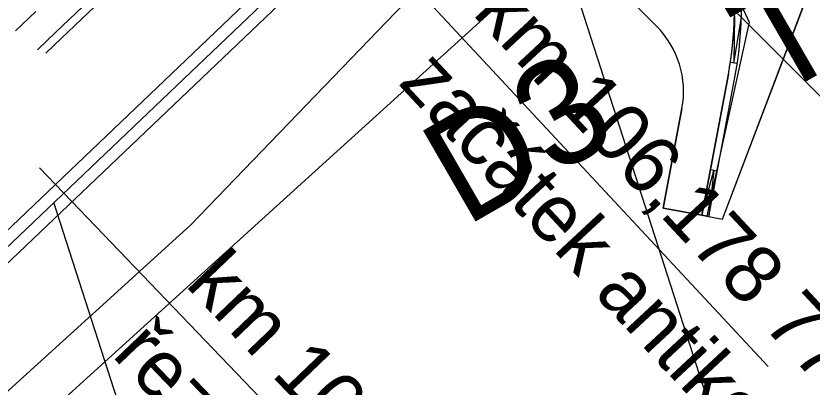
# Model space of a CAD drawing. Extents: x -759005 to -757278, y -1175311 to -1173953.
# Drawn here: x -758411.96 to -758394.73, y -1174860.97 to -1174852.94 of the extents above; entities that cross this region are included whole.
import ezdxf

# ---------------------------------------------------------------- set-up
doc = ezdxf.new("R2010")
doc.units = 0
for name, color, linetype in [('__NOR-dočasný zábor', 7, 'Continuous'), ('__NOR-trvalý zábor', 7, 'Continuous'), ('_NOR-návrh silná', 7, 'Continuous'), ('_NOR-návrh tenká', 7, 'Continuous'), ('_NOR-popis', 7, 'Continuous'), ('_NOR-sanace', 7, 'Continuous'), ('G_Obvod stavby', 7, 'Continuous')]:
    doc.layers.add(name, color=color, linetype=linetype)

msp = doc.modelspace()

# ---------------------------------------------------------------- linework, layer by layer
at = {"layer": '__NOR-dočasný zábor'}
for p, q in [((-758396.26, -1174852.717), (-758396.09, -1174853.08)), ((-758396.673, -1174857.339), (-758394.966, -1174852.852)), ((-758396.09, -1174853.08), (-758396.703, -1174855.869)), ((-758396.703, -1174855.869), (-758397.012, -1174857.276)), ((-758397.012, -1174857.276), (-758396.673, -1174857.339))]:
    msp.add_line(p, q, dxfattribs=at)
for points in [[(-758400.066, -1174851.383), (-758399.71, -1174851.06), (-758399.139, -1174850.214), (-758397.119, -1174852.234), (-758396.412, -1174852.941), (-758396.412, -1174852.941)], [(-758398.099, -1174853.163), (-758399.469, -1174851.794)], [(-758396.544, -1174854.202), (-758397.115, -1174857.256), (-758397.951, -1174857.1), (-758397.548, -1174854.945)]]:
    msp.add_lwpolyline(points, dxfattribs=at)
for centre, radius, end in [((-758404.26, -1174852.758), 7.85, 358.6622), ((-758399.514, -1174854.577), 2, 45)]:
    msp.add_arc(centre, radius, 349.3996, end, dxfattribs=at)
at = {"layer": '__NOR-trvalý zábor'}
for p, q in [((-758396.26, -1174852.717), (-758396.09, -1174853.08)), ((-758396.09, -1174853.08), (-758396.703, -1174855.869)), ((-758396.931, -1174856.274), (-758396.544, -1174854.202)), ((-758396.703, -1174855.869), (-758396.798, -1174856.299)), ((-758397.115, -1174857.256), (-758396.931, -1174856.274)), ((-758396.798, -1174856.299), (-758396.921, -1174856.86)), ((-758396.921, -1174856.86), (-758397.012, -1174857.276)), ((-758397.012, -1174857.276), (-758397.115, -1174857.256))]:
    msp.add_line(p, q, dxfattribs=at)
msp.add_arc((-758404.26, -1174852.758), 7.85, 349.3996, 358.6622, dxfattribs=at)
at = {"layer": '_NOR-návrh silná'}
msp.add_lwpolyline([(-758396.968, -1174857.284), (-758396.396, -1174854.23)], dxfattribs=at)
msp.add_arc((-758404.26, -1174852.758), 8, 349.3996, 52.6885, dxfattribs=at)
at = {"layer": '_NOR-návrh tenká'}
for p, q in [((-758399.229, -1174850.124), (-758396.412, -1174852.941)), ((-758419.775, -1174864.854), (-758406.31, -1174852.017)), ((-758419.596, -1174865.042), (-758406.131, -1174852.205)), ((-758396.412, -1174852.941), (-758397.091, -1174852.206)), ((-758419.417, -1174865.23), (-758405.951, -1174852.393)), ((-758408.177, -1174857.467), (-758403.548, -1174852.667)), ((-758396.41, -1174852.83), (-758396.263, -1174852.977)), ((-758396.412, -1174852.941), (-758396.427, -1174853.961)), ((-758396.427, -1174853.961), (-758396.263, -1174852.977)), ((-758392.771, -1174856.469), (-758396.263, -1174852.977)), ((-758396.353, -1174853.972), (-758396.501, -1174853.949)), ((-758397.115, -1174857.256), (-758396.858, -1174856.287)), ((-758396.858, -1174856.287), (-758396.968, -1174857.284)), ((-758396.784, -1174856.301), (-758396.931, -1174856.274)), ((-758418.166, -1174866.541), (-758408.177, -1174857.467))]:
    msp.add_line(p, q, dxfattribs=at)
for points in [[(-758396.968, -1174857.284), (-758396.673, -1174857.339), (-758390.499, -1174841.114), (-758389.088, -1174839.467), (-758389.316, -1174839.272)], [(-758411.492, -1174853.672), (-758411.096, -1174853.294), (-758410.375, -1174852.608), (-758409.654, -1174851.923), (-758408.931, -1174851.24), (-758408.207, -1174850.559), (-758407.482, -1174849.878), (-758406.756, -1174849.2), (-758406.029, -1174848.523), (-758405.3, -1174847.847), (-758405.192, -1174847.748)], [(-758411.313, -1174853.75), (-758410.971, -1174853.424), (-758410.251, -1174852.738), (-758409.53, -1174852.054), (-758408.807, -1174851.371), (-758408.084, -1174850.69), (-758407.359, -1174850.01), (-758406.633, -1174849.331), (-758405.906, -1174848.655), (-758405.178, -1174847.979), (-758405.047, -1174847.858)], [(-758398.099, -1174853.163), (-758399.469, -1174851.794)], [(-758396.968, -1174857.284), (-758397.115, -1174857.256), (-758396.544, -1174854.202)], [(-758397.115, -1174857.256), (-758397.951, -1174857.1), (-758397.548, -1174854.945)]]:
    msp.add_lwpolyline(points, dxfattribs=at)
for centre, radius, end in [((-758404.26, -1174852.758), 7.85, 52.6885), ((-758399.514, -1174854.577), 2, 45)]:
    msp.add_arc(centre, radius, 349.3996, end, dxfattribs=at)
at = {"layer": '_NOR-popis'}
for p, q in [((-758403.828, -1174851.775), (-758395.679, -1174860.526)), ((-758411.446, -1174856.231), (-758410.061, -1174857.674)), ((-758410.061, -1174857.674), (-758401.913, -1174866.157))]:
    msp.add_line(p, q, dxfattribs=at)
for points in [[(-758398.823, -1174886.544), (-758389.781, -1174883.631), (-758402.76, -1174843.338)], [(-758412.406, -1174884.035), (-758403.364, -1174881.122), (-758411.14, -1174856.98)]]:
    msp.add_lwpolyline(points, dxfattribs=at)
at = {"layer": '_NOR-sanace'}
msp.add_lwpolyline([(-758411.964, -1174853.265), (-758411.523, -1174852.845)], dxfattribs=at)
at = {"layer": 'G_Obvod stavby'}
for p, q in [((-758397.548, -1174854.945), (-758397.951, -1174857.1)), ((-758397.951, -1174857.1), (-758397.115, -1174857.256))]:
    msp.add_line(p, q, dxfattribs=at)
for points in [[(-758397.115, -1174857.256), (-758396.673, -1174857.339), (-758394.966, -1174852.852), (-758392.882, -1174847.378), (-758392.028, -1174845.133), (-758391.423, -1174843.542), (-758390.499, -1174841.114), (-758389.088, -1174839.467), (-758389.316, -1174839.272), (-758390.315, -1174838.9)], [(-758457.56, -1174867.46), (-758444.33, -1174881.69), (-758438.77, -1174887.67), (-758435.375, -1174884.045), (-758431.98, -1174880.42), (-758414.84, -1174864.78), (-758400.066, -1174851.383)], [(-758399.469, -1174851.794), (-758398.099, -1174853.163)]]:
    msp.add_lwpolyline(points, dxfattribs=at)
msp.add_arc((-758399.514, -1174854.577), 2, 349.3996, 45, dxfattribs=at)

# ---------------------------------------------------------------- texts
at = {"layer": '__NOR-dočasný zábor'}
msp.add_text('D3', height=2.2727, rotation=30, dxfattribs=at).set_placement((-758402.229, -1174857.516))
at = {"layer": '__NOR-trvalý zábor'}
msp.add_text('T1', height=2.2727, rotation=30, dxfattribs=at).set_placement((-758395.551, -1174854.759))
at = {"layer": '_NOR-popis'}
for s, rotation, p in [('km 106,178 779', 312.9634, (-758402.099, -1174852.898)), ('začátek antikorozní úpravy upevňovadel', 312.9634, (-758403.709, -1174854.398)), ('km 106,170 091', 313.8418, (-758408.315, -1174858.77)), ('řez a svár,', 313.8418, (-758409.901, -1174860.294))]:
    msp.add_text(s, height=1.25, rotation=rotation, dxfattribs=at).set_placement(p)

doc.saveas('drawing.dxf')
